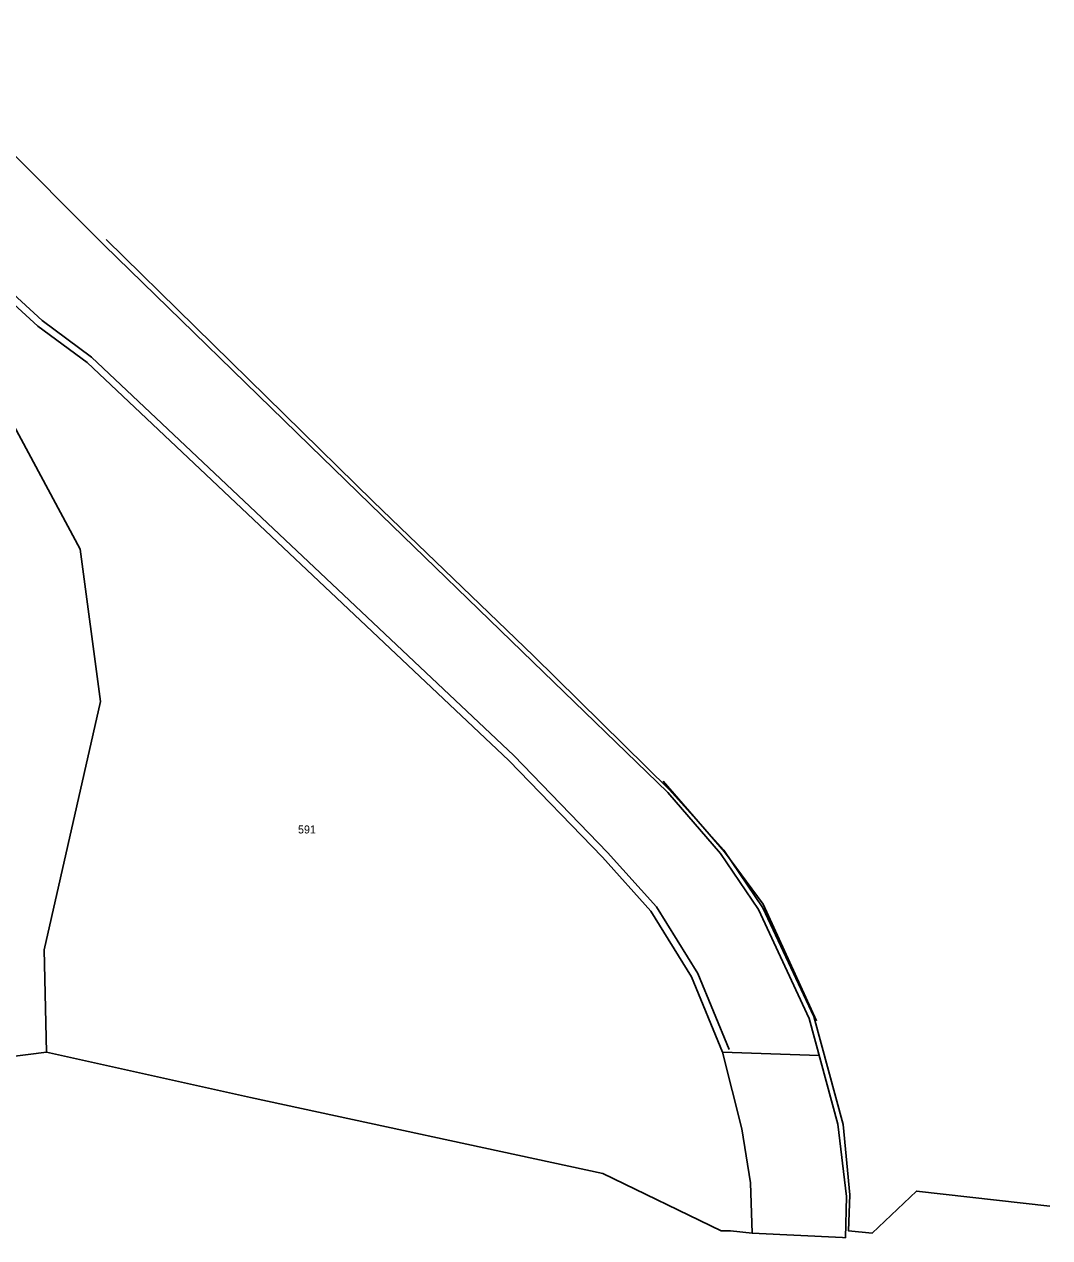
# Model space of a CAD drawing. Extents: x -882150 to -879379, y -1022570 to -1019819.
# Drawn here: x -880409 to -880191.2, y -1022570 to -1022312.2 of the extents above; entities that cross this region are included whole.
import ezdxf

# ---------------------------------------------------------------- set-up
doc = ezdxf.new("R2010")
doc.units = 0
for name, color, linetype in [('Hranice parcel', 7, 'Continuous'), ('Parcelní čísla', 7, 'Continuous'), ('Vnitřní kresba', 7, 'Continuous')]:
    doc.layers.add(name, color=color, linetype=linetype)

msp = doc.modelspace()

# ---------------------------------------------------------------- linework, layer by layer
at = {"layer": 'Hranice parcel'}
for p, q in [((-880391.99, -1022359.17), (-880438.9, -1022312.23)), ((-880345.66, -1022404.32), (-880391.99, -1022359.17)), ((-880343.36, -1022406.56), (-880345.66, -1022404.32)), ((-880335.48, -1022414.24), (-880343.36, -1022406.56)), ((-880260.96, -1022568.52), (-880258.98, -1022568.52)), ((-880258.98, -1022568.52), (-880254.4, -1022569)), ((-880254.4, -1022569), (-880235.23, -1022569.97)), ((-880234.6, -1022570), (-880235.23, -1022569.97))]:
    msp.add_line(p, q, dxfattribs=at)
for points in [[(-880404.24, -1022530.56), (-880404.73, -1022508.83), (-880392.77, -1022456.11), (-880397.13, -1022423.7), (-880438.43, -1022346.79), (-880406.13, -1022376.33), (-880395.66, -1022384.1), (-880306.08, -1022468.64), (-880286.2, -1022489.18), (-880275.92, -1022500.64), (-880267.29, -1022514.55), (-880260.67, -1022530.6), (-880256.57, -1022546.88), (-880254.74, -1022558.34), (-880254.4, -1022569)], [(-880234.6, -1022570), (-880234.38, -1022561.23), (-880236.2, -1022545.85), (-880242.27, -1022523.44), (-880253.08, -1022500.29), (-880261.13, -1022488.37), (-880272.31, -1022475.43), (-880300.95, -1022447.69), (-880335.48, -1022414.24)], [(-880998.2, -1022517.1), (-880952.02, -1022516.52), (-880884.86, -1022515.58), (-880845.4, -1022512.28), (-880791.54, -1022507.64), (-880731.9, -1022512.26), (-880686.58, -1022515.6), (-880574.8, -1022523.88), (-880551.94, -1022525.52), (-880465.31, -1022531.94), (-880433.72, -1022534.28), (-880421.61, -1022532.75), (-880404.24, -1022530.56)], [(-880404.24, -1022530.56), (-880360.92, -1022540.2), (-880286.08, -1022556.38), (-880260.96, -1022568.52)]]:
    msp.add_lwpolyline(points, dxfattribs=at)
at = {"layer": 'Vnitřní kresba'}
for p, q in [((-880405.18, -1022375.17), (-880437.42, -1022345.68)), ((-880394.7, -1022382.95), (-880405.18, -1022375.17)), ((-880305.03, -1022467.57), (-880394.7, -1022382.95)), ((-880285.09, -1022488.17), (-880305.03, -1022467.57)), ((-880274.71, -1022499.74), (-880285.09, -1022488.17)), ((-880265.95, -1022513.86), (-880274.71, -1022499.74)), ((-880259.28, -1022530.03), (-880265.95, -1022513.86)), ((-880260.67, -1022530.6), (-880240.14, -1022531.29))]:
    msp.add_line(p, q, dxfattribs=at)
for points in [[(-880391.59, -1022357.95), (-880334.87, -1022413.59), (-880300.84, -1022446.36), (-880272, -1022474.79), (-880260.4, -1022487.68), (-880252.13, -1022499.93), (-880241.28, -1022523.04), (-880235.08, -1022545.94), (-880233.65, -1022560.9), (-880233.97, -1022568.53), (-880228.88, -1022569.01), (-880219.5, -1022560.1), (-880191.2, -1022563.28)], [(-880273.27, -1022473.04), (-880260.3, -1022488.06), (-880252.03, -1022499.16), (-880240.72, -1022523.95)]]:
    msp.add_lwpolyline(points, dxfattribs=at)

# ---------------------------------------------------------------- texts
at = {"layer": 'Parcelní čísla'}
msp.add_text('591', height=1.7, dxfattribs=at).set_placement((-880350.85, -1022484.12))

doc.saveas('drawing.dxf')
